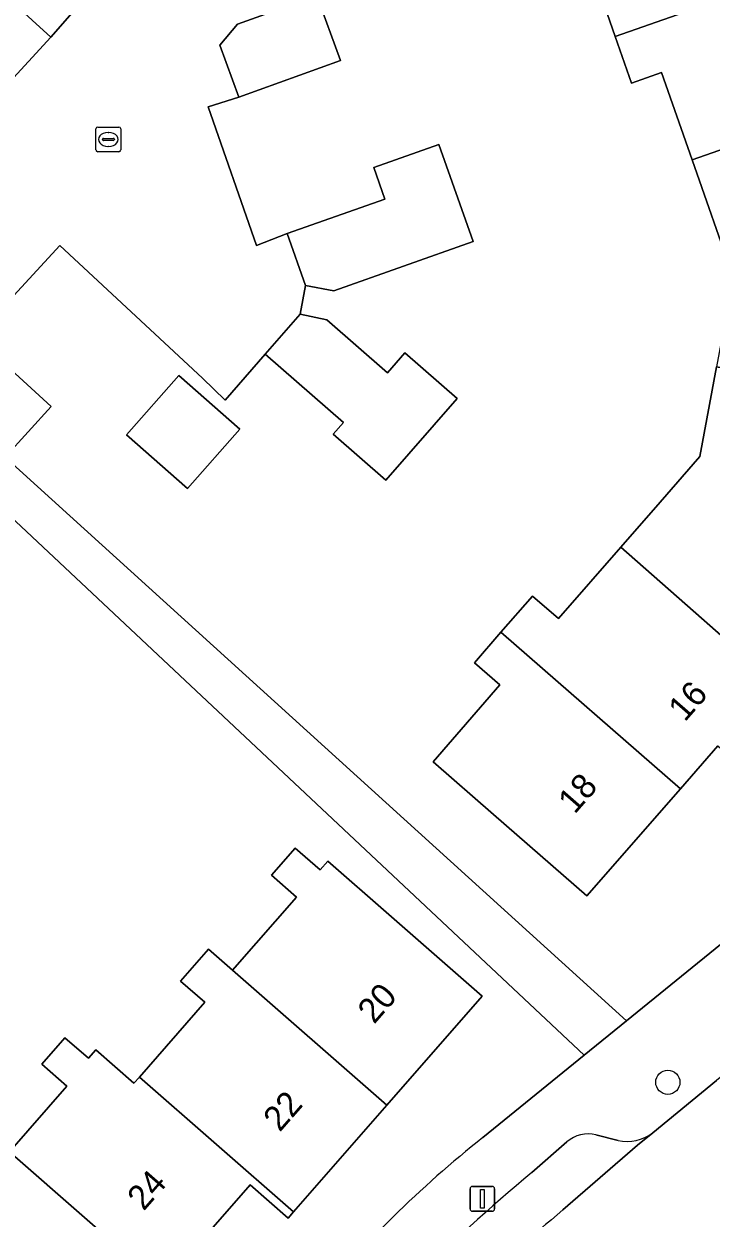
# Model space of a CAD drawing. Extents: x 158472 to 159562, y 388525 to 389606.
# Drawn here: x 158856.42 to 158884.17, y 388971.09 to 389019.31 of the extents above; entities that cross this region are included whole.
import ezdxf

# ---------------------------------------------------------------- set-up
doc = ezdxf.new("R2010")
doc.units = 0
for name, color, linetype in [('IMGEO_Boom', 7, 'Continuous'), ('IMGEO_Erf', 7, 'Continuous'), ('IMGEO_Kolk', 7, 'Continuous'), ('IMGEO_Lichtmast', 7, 'Continuous'), ('IMGEO_Pand', 7, 'Continuous'), ('IMGEO_Pand_nummerreeks', 7, 'Continuous'), ('IMGEO_Parkeervlak_open', 7, 'Continuous'), ('IMGEO_Rijbaan_lokaal_open', 7, 'Continuous'), ('IMGEO_Voetpad_open', 7, 'Continuous')]:
    doc.layers.add(name, color=color, linetype=linetype)

msp = doc.modelspace()

# ---------------------------------------------------------------- linework, layer by layer
at = {"layer": 'IMGEO_Boom'}
msp.add_circle((158882.424, 388976.575), 0.489, dxfattribs=at)
at = {"layer": 'IMGEO_Erf'}
for points in [[(158854.338, 389021.671), (158857.503, 389018.768), (158859.521, 389021.067), (158856.423, 389023.933), (158858.324, 389025.989), (158861.422, 389023.122), (158863.262, 389025.273), (158861.932, 389029.239), (158864.666, 389030.156), (158867.499, 389031.118), (158868.84, 389027.268), (158865.98, 389026.238), (158865.996, 389026.189), (158868.906, 389027.26), (158868.395, 389028.707), (158875.107, 389030.976), (158876.086, 389028.287), (158891.149, 389033.581), (158887.717, 389043.445), (158882.492, 389058.35), (158880.543, 389059.085), (158818.621, 389037.472)], [(158868.252, 389020.455), (158869.201, 389017.827), (158865.099, 389016.345), (158863.862, 389015.957), (158865.809, 389010.363), (158867.048, 389010.84), (158870.997, 389012.235), (158870.547, 389013.511), (158873.179, 389014.441), (158874.565, 389010.517), (158868.933, 389008.527), (158867.789, 389008.74), (158867.573, 389007.58), (158868.66, 389007.364), (158871.102, 389005.224), (158871.805, 389006.026), (158873.914, 389004.177), (158871.033, 389000.889), (158868.913, 389002.747), (158869.322, 389003.214), (158866.168, 389005.977), (158864.554, 389004.11), (158863.63, 389005.002), (158857.872, 389010.355), (158854.449, 389006.658), (158857.526, 389003.854), (158855.665, 389001.812), (158880.758, 388979.06), (158900.808, 388995.343)], [(158885.06, 389009.082), (158883.405, 389013.821), (158882.175, 389017.341), (158880.956, 389016.915), (158880.296, 389018.804), (158879.753, 389020.358)], [(158884.437, 388990.155), (158882.929, 388988.426), (158879.154, 388984.099), (158875.387, 388987.386), (158872.945, 388989.517), (158875.646, 388992.614), (158874.616, 388993.513), (158875.687, 388994.741), (158876.964, 388996.204), (158878.007, 388995.293), (158880.522, 388998.175), (158882.114, 389000), (158883.715, 389001.836), (158884.387, 389005.459)], [(158874.958, 388974.35), (158879.049, 388977.672), (158852.546, 389002.543)], [(158855.844, 388973.765), (158858.161, 388976.415), (158857.142, 388977.306), (158858.075, 388978.373), (158859.025, 388977.542), (158859.322, 388977.883), (158860.865, 388976.534), (158861.086, 388976.786), (158863.723, 388979.803), (158862.743, 388980.66), (158863.875, 388981.954), (158864.851, 388981.101), (158864.943, 388981.206), (158867.43, 388984.051), (158866.421, 388984.933), (158867.377, 388986.026), (158868.383, 388985.146), (158868.695, 388985.503), (158871.163, 388983.345), (158874.927, 388980.054), (158871.08, 388975.653), (158867.311, 388971.342), (158867.094, 388971.093), (158865.559, 388972.435), (158862.008, 388968.374)]]:
    msp.add_lwpolyline(points, dxfattribs=at)
msp.add_lwpolyline([(158860.567, 389002.709), (158862.683, 389005.115), (158865.147, 389002.949), (158863.032, 389000.543)], close=True, dxfattribs=at)
msp.add_arc((158904.883, 388936.872), 47.959, 128.6071, 140.1871, dxfattribs=at)
at = {"layer": 'IMGEO_Kolk'}
for p, q in [((158859.407, 389015.141), (158860.259, 389015.141)), ((158859.332, 389014.215), (158859.332, 389015.067)), ((158859.591, 389014.635), (158859.591, 389014.647)), ((158859.634, 389014.684), (158860.032, 389014.684)), ((158859.82, 389014.921), (158859.845, 389014.921)), ((158860.075, 389014.647), (158860.075, 389014.635)), ((158860.333, 389015.067), (158860.333, 389014.215)), ((158860.029, 389014.598), (158859.631, 389014.598)), ((158859.843, 389014.361), (158859.818, 389014.361)), ((158860.259, 389014.141), (158859.407, 389014.141))]:
    msp.add_line(p, q, dxfattribs=at)
for points in [[(158859.407, 389015.141), (158860.259, 389015.141)], [(158859.332, 389014.215), (158859.332, 389015.067)], [(158860.333, 389015.067), (158860.333, 389014.215)], [(158860.259, 389014.141), (158859.407, 389014.141)]]:
    msp.add_lwpolyline(points, dxfattribs=at)
for centre, radius, start, end in [((158859.409, 389015.065), 0.0765, 91.552, 178.448), ((158859.409, 389015.065), 0.0765, 91.552, 178.448), ((158860.257, 389015.065), 0.0765, 1.552, 88.448), ((158860.257, 389015.065), 0.0765, 1.552, 88.448), ((158859.631, 389014.644), 0.0403, 85.8775, 175.7526), ((158859.628, 389014.634), 0.0366, 178.938, 274.7102), ((158860.032, 389014.641), 0.043, 264.8664, 352.4533), ((158860.036, 389014.646), 0.0386, 1.7309, 96.639), ((158859.409, 389014.217), 0.0765, 181.552, 268.448), ((158859.409, 389014.217), 0.0765, 181.552, 268.448), ((158860.257, 389014.217), 0.0765, 271.552, 358.448), ((158860.257, 389014.217), 0.0765, 271.552, 358.448)]:
    msp.add_arc(centre, radius, start, end, dxfattribs=at)
for centre, major_axis, ratio, start_param, end_param in [((158859.819, 389014.641), (-0.387, 0.002), 0.722429, 4.712389, 7.853982), ((158859.844, 389014.641), (-0.39, 0.002), 0.717154, 1.570796, 4.712389)]:
    msp.add_ellipse(centre, major_axis=major_axis, ratio=ratio, start_param=start_param, end_param=end_param, dxfattribs=at)
at = {"layer": 'IMGEO_Lichtmast'}
for p, q in [((158874.44, 388971.467), (158874.44, 388972.267)), ((158874.44, 388972.267), (158874.44, 388971.467)), ((158874.54, 388972.367), (158875.33, 388972.367)), ((158875.33, 388972.367), (158874.54, 388972.367)), ((158875.43, 388972.267), (158875.43, 388971.467)), ((158875.43, 388971.467), (158875.43, 388972.267)), ((158875.33, 388971.367), (158874.54, 388971.367)), ((158874.54, 388971.367), (158875.33, 388971.367))]:
    msp.add_line(p, q, dxfattribs=at)
msp.add_lwpolyline([(158874.86, 388972.242), (158875.01, 388972.242), (158875.01, 388971.492), (158874.86, 388971.492), (158874.86, 388972.242)], dxfattribs=at)
for centre, start, end in [((158874.54, 388972.267), 90, 180), ((158874.54, 388972.267), 90, 180), ((158875.33, 388972.267), 0, 90), ((158875.33, 388972.267), 360, 90), ((158874.54, 388971.467), 180, 270), ((158874.54, 388971.467), 180, 270), ((158875.33, 388971.467), 270, 0), ((158875.33, 388971.467), 270, 0)]:
    msp.add_arc(centre, 0.1, start, end, dxfattribs=at)
at = {"layer": 'IMGEO_Pand'}
for points in [[(158889.458, 389022.008), (158888.82, 389023.835), (158889.617, 389024.114), (158888.366, 389027.695), (158879.754, 389024.686), (158881.102, 389020.83), (158879.753, 389020.358), (158880.296, 389018.804)], [(158883.405, 389013.821), (158892.166, 389016.883), (158891.027, 389020.143), (158890.209, 389019.858), (158889.458, 389022.008), (158880.296, 389018.804), (158880.956, 389016.915), (158882.175, 389017.341)], [(158855.709, 389016.811), (158857.503, 389018.768), (158854.338, 389021.671), (158852.543, 389019.715)], [(158868.252, 389020.455), (158865.05, 389019.299), (158864.338, 389018.454), (158865.099, 389016.345), (158869.201, 389017.827)], [(158892.166, 389016.883), (158883.405, 389013.821), (158885.06, 389009.082), (158884.387, 389005.459), (158891.14, 389004.206), (158891.716, 389007.178), (158892.008, 389008.72), (158896.008, 389010.117), (158893.483, 389017.343)], [(158867.789, 389008.74), (158868.933, 389008.527), (158874.565, 389010.517), (158873.179, 389014.441), (158870.547, 389013.511), (158870.997, 389012.235), (158867.048, 389010.84)], [(158866.168, 389005.977), (158869.322, 389003.214), (158868.913, 389002.747), (158871.033, 389000.889), (158873.914, 389004.177), (158871.805, 389006.026), (158871.102, 389005.224), (158868.66, 389007.364), (158867.573, 389007.58)], [(158852.588, 389004.616), (158855.665, 389001.812), (158857.526, 389003.854), (158854.449, 389006.658)], [(158860.567, 389002.709), (158863.032, 389000.543), (158865.147, 389002.949), (158862.683, 389005.115)], [(158891.14, 389004.206), (158884.387, 389005.459), (158883.715, 389001.836), (158882.114, 389000), (158880.522, 388998.175), (158887.379, 388992.153), (158888.465, 388991.199), (158893.481, 388996.949), (158890.268, 388999.752), (158890.317, 389000), (158890.569, 389001.288)], [(158880.522, 388998.175), (158878.007, 388995.293), (158876.964, 388996.204), (158875.687, 388994.741), (158882.929, 388988.426), (158884.437, 388990.155), (158885.117, 388989.561), (158887.379, 388992.153)], [(158882.929, 388988.426), (158875.687, 388994.741), (158874.616, 388993.513), (158875.646, 388992.614), (158872.945, 388989.517), (158875.387, 388987.386), (158879.154, 388984.099)], [(158864.851, 388981.101), (158871.08, 388975.653), (158874.927, 388980.054), (158871.163, 388983.345), (158868.695, 388985.503), (158868.383, 388985.146), (158867.377, 388986.026), (158866.421, 388984.933), (158867.43, 388984.051), (158864.943, 388981.206)], [(158864.851, 388981.101), (158863.875, 388981.954), (158862.743, 388980.66), (158863.723, 388979.803), (158861.086, 388976.786), (158867.311, 388971.342), (158871.08, 388975.653)], [(158861.086, 388976.786), (158860.865, 388976.534), (158859.322, 388977.883), (158859.025, 388977.542), (158858.075, 388978.373), (158857.142, 388977.306), (158858.161, 388976.415), (158855.844, 388973.765), (158862.008, 388968.374), (158865.559, 388972.435), (158867.094, 388971.093), (158867.311, 388971.342)], [(158855.844, 388973.765), (158855.598, 388973.484), (158854.599, 388974.358), (158853.404, 388972.991), (158854.386, 388972.133), (158852.057, 388969.469), (158858.239, 388964.062), (158862.008, 388968.374)]]:
    msp.add_lwpolyline(points, close=True, dxfattribs=at)
at = {"layer": 'IMGEO_Parkeervlak_open'}
for points in [[(158878.351, 388974.171), (158876.927, 388972.932)], [(158878.189, 388971.419), (158881.201, 388974.04), (158881.812, 388974.535)], [(158880.414, 388974.226), (158879.521, 388974.451)]]:
    msp.add_lwpolyline(points, dxfattribs=at)
for centre, radius, start, end in [((158879.203, 388973.194), 1.297, 75.8207, 131.0967), ((158880.78, 388975.885), 1.699, 257.5412, 307.3862), ((158924.102, 388916.357), 73.663, 129.82274, 134.98268), ((158924.006, 388916.47), 71.544, 129.82182, 137.63434)]:
    msp.add_arc(centre, radius, start, end, dxfattribs=at)
at = {"layer": 'IMGEO_Rijbaan_lokaal_open'}
for points in [[(158859.521, 389021.067), (158857.503, 389018.768), (158855.709, 389016.811)], [(158854.449, 389006.658), (158857.872, 389010.355), (158863.63, 389005.002), (158864.554, 389004.11), (158866.168, 389005.977), (158867.573, 389007.58), (158867.789, 389008.74), (158867.048, 389010.84), (158865.809, 389010.363), (158863.862, 389015.957), (158865.099, 389016.345), (158864.338, 389018.454), (158865.05, 389019.299), (158868.252, 389020.455)], [(158905.858, 388994.208), (158905.645, 388993.972), (158905.218, 388993.501), (158884.388, 388976.64), (158881.812, 388974.535), (158881.201, 388974.04), (158878.189, 388971.419)]]:
    msp.add_lwpolyline(points, dxfattribs=at)
msp.add_arc((158924.006, 388916.47), 71.544, 129.82182, 137.63434, dxfattribs=at)
at = {"layer": 'IMGEO_Voetpad_open'}
for points in [[(158884.528, 389060.496), (158880.543, 389059.085), (158882.492, 389058.35), (158887.717, 389043.445), (158891.149, 389033.581), (158892.343, 389030.156), (158902.86, 389000), (158900.808, 388995.343), (158880.758, 388979.06), (158879.049, 388977.672), (158874.958, 388974.35)], [(158881.812, 388974.535), (158884.388, 388976.64)], [(158876.927, 388972.932), (158878.351, 388974.171)], [(158879.521, 388974.451), (158880.414, 388974.226)]]:
    msp.add_lwpolyline(points, dxfattribs=at)
msp.add_lwpolyline([(158855.665, 389001.812), (158852.588, 389004.616), (158850.535, 389006.431), (158849.466, 389005.35), (158852.546, 389002.543), (158879.049, 388977.672), (158880.758, 388979.06)], close=True, dxfattribs=at)
for centre, radius, start, end in [((158904.883, 388936.872), 47.959, 128.6071, 140.1871), ((158879.203, 388973.194), 1.297, 75.8207, 131.0967), ((158880.78, 388975.885), 1.699, 257.5412, 307.3862), ((158924.102, 388916.357), 73.663, 129.82274, 134.98268)]:
    msp.add_arc(centre, radius, start, end, dxfattribs=at)

# ---------------------------------------------------------------- texts
at = {"layer": 'IMGEO_Pand_nummerreeks'}
for s, rotation, p in [('16', 48.8962, (158883.11, 388991.093)), ('18', 48.8976, (158878.661, 388987.367)), ('20', 48.8447, (158870.565, 388978.893)), ('22', 48.8389, (158866.754, 388974.535)), ('24', 48.8349, (158861.261, 388971.348))]:
    msp.add_text(s, height=1, rotation=rotation, dxfattribs=at).set_placement(p)

doc.saveas('drawing.dxf')
